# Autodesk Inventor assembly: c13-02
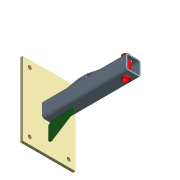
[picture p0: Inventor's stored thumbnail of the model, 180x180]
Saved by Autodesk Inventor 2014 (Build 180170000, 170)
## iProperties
Created: 2011-01
Part Number: c13-02
Document SubType Name: Weldment
Designer: Thom Tremblay
Weld Material: Welded Steel Mild
_SolveAssemblyDoc: Frame Generator Solve Assembly
_Version: 15.0.0
Author: Thom Tremblay
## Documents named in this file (5)
- C:\Inventor 2014 Essentials\Assemblies\Chapter 13\c13-02.iam
- C:\Inventor 2014 Essentials\Parts\Chapter 13\c13-01.ipt
- C:\Inventor 2014 Essentials\Parts\Chapter 13\c13-02.ipt
- C:\Inventor 2014 Essentials\Assemblies\Chapter 13\Frame\Frame c13-01.iam
- C:\Inventor 2014 Essentials\Parts\Chapter 13\c13-03.ipt
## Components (4 placed, 4 different names)
1. c13-01:1 — Mate:2
2. c13-02:1 — Flush:1
3. Frame c13-01:1 [sub-assembly] — Mate:3
4. c13-03:1 — Mate:1, Mate:2, Mate:3
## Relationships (4: Mate 3, Flush 1)
- Flush:1: c13-02:1
- Mate:1: c13-03:1
- Mate:2: c13-01:1 ↔ c13-03:1
- Mate:3: Frame c13-01:1 ↔ c13-03:1
